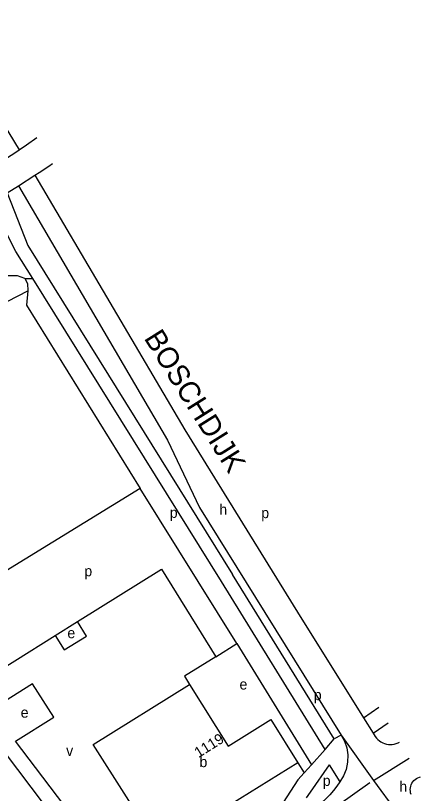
# Model space of a CAD drawing. Extents: x 156721 to 158827, y 386657 to 388950.
# Drawn here: x 157836.4 to 157990.2, y 388574.1 to 388869.5 of the extents above; entities that cross this region are included whole.
import ezdxf

# ---------------------------------------------------------------- set-up
doc = ezdxf.new("R2010")
doc.units = 0
for name, color, linetype in [('BLT_Basislijn', 7, 'Continuous'), ('BLT_Bebouwing', 7, 'Continuous'), ('BLT_Centroide', 7, 'Continuous'), ('BLT_Huisnummer_reeks', 7, 'Continuous'), ('BLT_Straatnaam_hoofdweg', 7, 'Continuous'), ('BLT_Vlakafsluiter', 7, 'Continuous')]:
    doc.layers.add(name, color=color, linetype=linetype)

msp = doc.modelspace()

# ---------------------------------------------------------------- linework, layer by layer
at = {"layer": 'BLT_Basislijn'}
for p, q in [((157806.29, 388869.46), (157837.84, 388818.52)), ((157839.95, 388769.64), (157842.91, 388769.68)), ((157914.58, 388654.54), (157842.91, 388769.68)), ((157755.59, 388720.4), (157841.04, 388764.99)), ((157883.73, 388689.91), (157813.29, 388646.72)), ((157920.4, 388630.97), (157883.73, 388689.91)), ((157906.29, 388682.69), (157960.09, 388596.26)), ((157891.84, 388659.23), (157912.52, 388626.01)), ((157957.4, 388594.81), (157918.82, 388657.17)), ((157954.04, 388590.73), (157914.58, 388654.54)), ((157943.46, 388642.9), (157968.59, 388602.78)), ((157851.43, 388634.02), (157859.9, 388639.35)), ((157912.52, 388626.01), (157920.4, 388630.97)), ((157920.4, 388630.97), (157948.82, 388585)), ((157968.59, 388602.78), (157974.33, 388606.88)), ((157968.59, 388602.78), (157972.23, 388596.96)), ((157972.23, 388596.96), (157977.86, 388600.97)), ((157960.09, 388596.26), (157957.4, 388594.81)), ((157972.23, 388596.96), (157973.01, 388595.71)), ((157954.04, 388590.73), (157948.82, 388585)), ((157943.66, 388585.67), (157945.99, 388581.9)), ((157948.82, 388585), (157945.99, 388581.9)), ((157955.54, 388585.02), (157948.27, 388574.59)), ((157955.54, 388585.02), (157959.58, 388578.52)), ((157943.56, 388579.24), (157938.08, 388570.62)), ((157970.91, 388578.09), (157958.64, 388569.41)), ((157948.27, 388574.59), (157946.73, 388572.37))]:
    msp.add_line(p, q, dxfattribs=at)
for points in [[(157837.84, 388818.52), (157840.62, 388820.4), (157844.5, 388823.12)], [(157831.47, 388814.36), (157831.95, 388814.66), (157836.18, 388817.4), (157837.84, 388818.52)], [(157843.74, 388808.8), (157845.39, 388809.84), (157849.01, 388812.31), (157850.41, 388813.31)], [(157837.52, 388804.87), (157843.74, 388808.8)], [(157843.74, 388808.8), (157900.67, 388712.11), (157943.46, 388642.9)], [(157833.21, 388802.15), (157837.52, 388804.87)], [(157837.52, 388804.87), (157894.12, 388708.24), (157906.29, 388682.69)], [(157833.21, 388802.15), (157841.02, 388782.18), (157918.82, 388657.17)], [(157842.91, 388769.68), (157836.53, 388779.93), (157832.06, 388788.59)], [(157839.95, 388769.64), (157837.2, 388770.62), (157832.95, 388770.62), (157747.04, 388724.27), (157732.32, 388719.81), (157729.65, 388719.1)], [(157839.95, 388769.64), (157840.98, 388767.76), (157841.04, 388764.99)], [(157841.04, 388764.99), (157840.52, 388759.54), (157883.73, 388689.91)], [(157859.9, 388639.35), (157891.84, 388659.23)], [(157851.43, 388634.02), (157854.86, 388628.68), (157863.38, 388633.84), (157859.9, 388639.35)], [(157820.65, 388614.78), (157851.43, 388634.02)], [(157912.52, 388626.01), (157900.57, 388618.57), (157902.5, 388615.47)], [(157836.41, 388593.96), (157850.9, 388603.03), (157842.9, 388615.75), (157827.28, 388606.02)], [(157817.1, 388609.55), (157872.27, 388536.72)], [(157960.09, 388596.26), (157961.32, 388593.98), (157962.18, 388591.42), (157962.59, 388588.7), (157962.51, 388585.92), (157961.94, 388583.23), (157960.94, 388580.73), (157959.58, 388578.52)], [(157973.01, 388595.71), (157973.47, 388595.12), (157973.99, 388594.58), (157974.56, 388594.1), (157975.18, 388593.68), (157975.84, 388593.33), (157976.54, 388593.06), (157977.26, 388592.86), (157977.99, 388592.74), (157978.74, 388592.69), (157979.49, 388592.73), (157980.23, 388592.85), (157980.95, 388593.04), (157981.65, 388593.31), (157982.25, 388593.62)], [(157877.21, 388540.06), (157868.9, 388551.04), (157860.59, 388562.02), (157852.28, 388573), (157843.97, 388583.98), (157836.41, 388593.96)], [(157945.99, 388581.9), (157943.56, 388579.24)], [(157986.64, 388573.72), (157986.45, 388574.32), (157986.33, 388574.94), (157986.3, 388575.57), (157986.34, 388576.19), (157986.46, 388576.81), (157986.67, 388577.41), (157986.94, 388577.97), (157987.29, 388578.5), (157987.69, 388578.98), (157988.16, 388579.41), (157988.67, 388579.77), (157989.23, 388580.06), (157989.82, 388580.28), (157990.17, 388580.36)], [(157959.58, 388578.52), (157958.38, 388576.82), (157957.09, 388575.17), (157955.7, 388573.6), (157954.23, 388572.1), (157952.67, 388570.69), (157951.05, 388569.37), (157949.36, 388568.15)]]:
    msp.add_lwpolyline(points, dxfattribs=at)
at = {"layer": 'BLT_Bebouwing'}
for points in [[(157943.66, 388585.67), (157914.19, 388567.45), (157914.49, 388566.97), (157908.34, 388563.13), (157908.08, 388563.55), (157891.16, 388552.94), (157865.87, 388592.62), (157902.5, 388615.47)], [(157902.5, 388615.47), (157917.09, 388592.1), (157933.32, 388602.2), (157943.66, 388585.67)]]:
    msp.add_lwpolyline(points, dxfattribs=at)
at = {"layer": 'BLT_Vlakafsluiter'}
for p, q in [((157954.04, 388590.73), (157957.4, 388594.81)), ((157960.09, 388596.26), (157972.37, 388579.02)), ((157972.37, 388579.02), (157985.9, 388587.52)), ((157972.37, 388579.02), (157982.69, 388565.04))]:
    msp.add_line(p, q, dxfattribs=at)

# ---------------------------------------------------------------- texts
at = {"layer": 'BLT_Centroide'}
for s, p in [('h', (157913.78, 388679.93)), ('p', (157894.96, 388678.73)), ('p', (157929.73, 388678.64)), ('p', (157862.53, 388656.56)), ('e', (157856.1, 388633.04)), ('e', (157921.46, 388613.55)), ('p', (157949.67, 388609.52)), ('e', (157838.37, 388602.86)), ('v', (157855.63, 388588.35)), ('b', (157906.25, 388584.09)), ('p', (157953.06, 388576.96)), ('h', (157982.14, 388574.74))]:
    msp.add_text(s, height=4, dxfattribs=at).set_placement(p)
at = {"layer": 'BLT_Huisnummer_reeks'}
msp.add_text('1119', height=4, rotation=31.9598, dxfattribs=at).set_placement((157905.88, 388587.49))
at = {"layer": 'BLT_Straatnaam_hoofdweg'}
msp.add_text('BOSCHDIJK', height=8, rotation=302.0908, dxfattribs=at).set_placement((157884.98, 388746.97))

doc.saveas('drawing.dxf')
